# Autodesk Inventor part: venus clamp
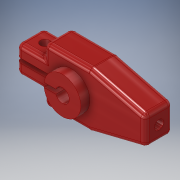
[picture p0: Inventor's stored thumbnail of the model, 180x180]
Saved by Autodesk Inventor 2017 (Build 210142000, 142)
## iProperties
Created: 2016-05
Part Number: venus clamp
Material: Generic
Document SubType Name: Modeling
Designer: Stan
Density: 1 g/cm^3
Appearance: Red
Author: Stan
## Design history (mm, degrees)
sketch "Sketch1"
  geometry: L1 (-9.525, 9.525)-(6.35, 9.525); L2 (6.35, -9.463)-(-9.525, -9.463); L3 (25.4, 4.763)-(25.4, -4.763); L4 (25.4, -4.763)-(6.35, -9.463); L5 (25.4, 4.763)-(6.35, 9.525); L6 (-9.525, 9.525)-(-9.525, 4.763); L7 (-9.525, 4.763)-(-19.05, 4.762); L8 (-19.05, -4.7)-(-9.525, -4.7); L9 (-9.525, -4.7)-(-9.525, -9.463); L10 (-2.256, 0.762)-(-19.05, 0.762); L11 (-2.256, -0.762)-(-19.05, -0.762); L12 (-19.05, -4.7)-(-19.05, -0.762); L13 (-19.05, 0.762)-(-19.05, 4.762); A1 r 2.381 centre (0, 0) between (-2.256, -0.762) and (-2.256, 0.762); 1 further point
  constraints: 26 end point, 4 perpendicular, 2 point on circle, 2 point on line, 2 vertical, 1 centre point, 1 coincident, 1 horizontal, 1 parallel
  dimensions: "d1" = 9.525 distance from line of L1 point (0, 0); "d2" = 25.4 horizontal distance of L3.end point (0, 0); "d4" = 9.525 distance of L3.start L3.end; "d5" = 4.7625 vertical distance of point (0, 0) L3.start; "d7" = 4.7625 diameter of A1; "d8" = 19.05 horizontal distance of L8.start point (0, 0); "d11" = 9.525 distance from line of point (0, 0) L6; "d12" = 19.05 distance from line of point (0, 0) L13; "d14" = 1.524 distance between parallel lines of L11 L10; "d15" = 0.762 distance from line of L10 point (0, 0); "d16" = 15.875 distance of L1.start L1.end; "d17" = 15.875 distance of L2.start L2.end; "d18" = 4.7625 distance between parallel lines of L2 L8; "d19" = 4.7625 distance between parallel lines of L7 L1
extrude "Extrusion1" new body sketch "Sketch1" distance "d20" = 9.525; taper "d21" = 0 deg
fillet "Fillet1" dims "d22" = 1.5875
sketch "Sketch2"
  geometry: C1 r 1.587 at (3.175, 3.519); 1 further point
  constraints: 1 centre point
  dimensions: "d23" = 3.175 diameter of C1
extrude "Extrusion2" cut sketch "Sketch2" distance "d24" = 15.875; taper "d25" = 0 deg
sketch "Sketch3"
  geometry: L1 (-1.587, 6.35)-(-1.588, 0) reference; C1 r 1.587 at (3.492, 3.175); 1 further point
  constraints: 1 centre point
  dimensions: "d26" = 3.175 diameter of C1; "d27" = 5.08 distance from line of C1.centre L1
extrude "Extrusion3" cut sketch "Sketch3" distance "d28" = 9.525; taper "d29" = 0 deg
fillet "Fillet2" dims "d30" = 1.5875
fillet "Fillet3" dims "d31" = 1.5875
sketch "Sketch4"
  geometry: L1 (-2.256, 0.762)-(-6.304, 0.762); L2 (-17.462, 0.762)-(-2.256, 0.762) reference; L3 (-2.256, -0.762)-(-6.304, -0.762); A1 r 6.35 centre (0, 0) between (-6.304, -0.762) and (-6.304, 0.762); A2 r 2.381 centre (0, 0) between (-2.256, -0.762) and (-2.256, 0.762); 1 further point
  constraints: 5 end point, 4 point on circle, 2 centre point, 2 coincident, 1 parallel, 1 point on line
  dimensions: "d32" = 12.7 diameter of A1
extrude "Extrusion4" join sketch "Sketch4" distance "d33" = 3.175; taper "d34" = 0 deg
body "Solid1"
